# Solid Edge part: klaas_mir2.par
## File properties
Last saved by: Cymax
Revision: 52
Accuracy: 0,990
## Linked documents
klaas_mir.par
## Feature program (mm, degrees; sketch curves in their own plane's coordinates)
part copy "CopiedPart_1"
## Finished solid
Body 1: solid body, 39 faces, 96 edges, 64 vertices.
  Faces by surface: plane 23, cylinder 8, torus 8
  Edges by curve: line 56, circle 28, intersection 12
Bounding box of the edges (mm; curved faces can reach further): 1221.056 x 180.674 x 352.473, from (235.5991, -707.4018, -344.4289) to (1456.6554, -526.7275, 8.0446).
Cylindrical faces by radius (mm): R430.6294 x1, R437.3201 x1, R450.6294 x1, R457.3201 x1, R658.028 x2, R678.028 x2
Toroidal faces (ring radius, tube radius in mm): R478.028 r180 x4, R478.028 r200 x4
Planar faces by outward normal: +x 6, -x 6, oblique 11
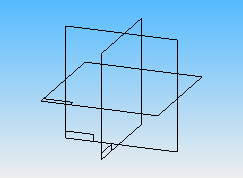
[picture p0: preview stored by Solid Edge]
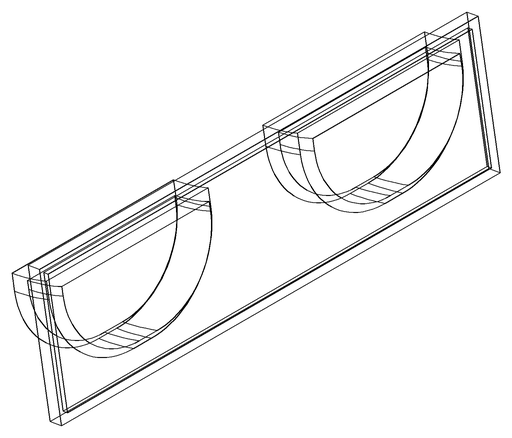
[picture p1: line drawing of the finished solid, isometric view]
